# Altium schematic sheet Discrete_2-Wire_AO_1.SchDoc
size 431 x 279 mm; Date: Not shown in title block; ApprovedBy: Not shown in title block; CheckedBy: Not shown in title block; Author: Not shown in title block; CompanyName: Not shown in title block; Engineer: Not shown in title block; Organization: Not shown in title block; Address1: Not shown in title block; Address2: Not shown in title block; Address3: Not shown in title block; Address4: Not shown in title block; DocumentNumber: 1; Revision: Use project parameter SCH_Rev; SheetNumber: 1; SheetTotal: 1; PageSetup: Record=PageOptions|CenterHorizontal=True|CenterVertical=True|PrintScale=1.00|XCorrection=1.00|YCorrection=1.00|PrintKind=0|BorderSize=5000000|LeftOffset=0|BottomOffset=0|Orientation=2|PaperLength=1000|PaperWidth=1000|Scale=100|PaperSource=15|PrintQuality=600|MediaType=1|DitherType=10|PaperKind=Letter|PrintScaleMode=1
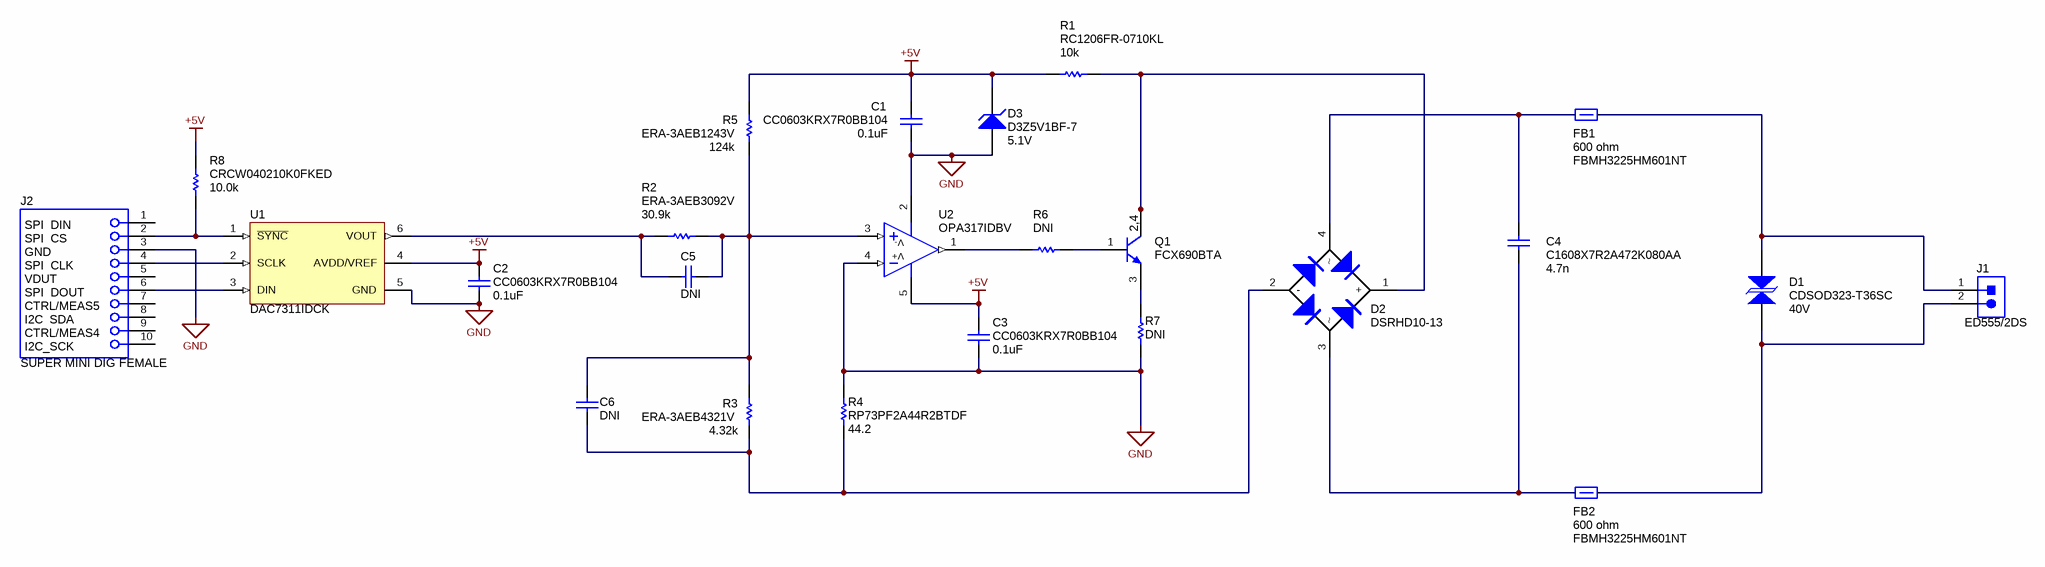
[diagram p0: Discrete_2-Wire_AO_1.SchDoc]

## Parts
C1  CC0603KRX7R0BB104  value 0.1uF  [0603]
C2  CC0603KRX7R0BB104  value 0.1uF  [0603]
C3  CC0603KRX7R0BB104  value 0.1uF  [0603]
C4  C1608X7R2A472K080AA  value 4.7n  [0603]
C5  DNI  [0603]
C6  DNI  [0603]
D1  CDSOD323-T36SC  value 40V  [sod-323]
D2  DSRHD10-13  [T-MiniDIP]
D3  D3Z5V1BF-7  value 5.1V  [SOD-323F]
FB1  FBMH3225HM601NT  value 600 ohm  [1210_H25]
FB2  FBMH3225HM601NT  value 600 ohm  [1210_H25]
J1  ED555/2DS  [TERM_BLK_ED555-2DS]
J2  SUPER MINI DIG FEMALE  [CONN_851-43-010-20-001000]
Q1  FCX690BTA  [SOT-89-3]
R1  RC1206FR-0710KL  value 10k  [1210]
R2  ERA-3AEB3092V  value 30.9k  [0603]
R3  ERA-3AEB4321V  value 4.32k  [0603]
R4  RP73PF2A44R2BTDF  value 44.2  [0805]
R5  ERA-3AEB1243V  value 124k  [0603]
R6  DNI  [0603]
R7  DNI  [0603]
R8  CRCW040210K0FKED  value 10.0k  [0402]
U1  DAC7311IDCK  [DCK0006A_N]
U2  OPA317IDBV  [DBV0005A_N]

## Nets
+5V: C1.1 C2.1 C3.1 D3.1(K) R1.1 R5.2 R8.2 U1.4(AVDD/VREF) U2.5(V+)
GND: C1.2 C2.2 C3.2 D3.2(A) J2.3 R4.2 R7.1 U1.5(GND) U2.2(V-) U2.4(IN-)
NetC4_1: C4.1 D2.4 FB1.1
NetC4_2: C4.2 D2.3 FB2.1
NetC5_1: C5.1 R2.1 U1.6(VOUT)
NetC5_2: C5.2 C6.1 R2.2 R3.2 R5.1 U2.3(IN+)
NetC6_2: C6.2 D2.2(-) R3.1 R4.1
NetD1_1: D1.1 FB1.2 J1.1
NetD1_2: D1.2 FB2.2 J1.2
NetD2_1: D2.1(+) Q1.2(C) Q1.4(C) R1.2
NetJ2_2: J2.2 R8.1 U1.1(~{SYNC})
NetJ2_4: J2.4 U1.2(SCLK)
NetJ2_6: J2.6 U1.3(DIN)
NetQ1_1: Q1.1(B) R6.2
NetQ1_3: Q1.3(E) R7.2
NetR6_1: R6.1 U2.1(OUT)

Not connected (* = marked no-connect by the designer): J2 1 5 7 8 9 10

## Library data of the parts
C1-C3 = Capacitor: CAP CER 0.1UF 100V 10% X7R 0603; Manufacturer: Yageo; Polarized: N; U/M: EA
C4 = Capacitor: CAP CER 4700PF 100V 10% X7R 0603; Manufacturer: TDK; Polarized: N; U/M: EA
C5 C6 = GRM188R72A102KA01D: CompType: Capacitor
D1 = SMAJ15CA: TVS DIODE 36VWM 60VC SOD323; Manufacturer: Bourns Inc
D2 = DSRHD10-13: Diode, Switching-Bridge, 1000V, 1A, 5.0x1.21x6.2mm; Manufacturer: Diodes Inc.; U/M: EA; Vf_V: 1.15; Value2: 1.15V; Io_A: 1; Vr_V: 1000; TJmax_C: 150
D3 = D3Z5V1BF-7: Diode, Zener, 5.1V, 400mW, SOD-323F; Manufacturer: Diodes Inc.; SymbolCreator: a0412235; U/M: EA; Power_W: 0.4; Vz_V: 5.1; Value1: 0.4W; RJA_CperW: 313
FB1 FB2 = FBMH3225HM601NT: 3A Ferrite Bead, 600 ohm @ 100MHz, SMD; Manufacturer: Taiyo Yuden; Imax_A: 3; DCR_ohm: 0.042; Value1: 0.042 ohm; ZTyp@100MHz_Ohm: 600; U/M: EA
J1 = ED555/2DS: Terminal Block, 6A, 3.5mm Pitch, 2-Pos, TH; Manufacturer: On-Shore Technology; SymbolCreator: a0412235; CompType: Connector; U/M: EA
J2 = 851-43-010-20-001000: Receptacle, 50mil 10x1, R/A, TH; Manufacturer: Mill-Max; SymbolCreator: a0411947; U/M: EA
Q1 = FCX690BTA, Diodes Inc.: Transistor, NPN, 45V, 1A, SOT-89; CompType: BJT; PNP: 0; NPN: 1; Vceo_V: 45; Vcesat1_V: 0.08; Value: 0.08V; TaMin_C: -55; TaMax_C: 150; U/M: EA
R1 = Resistor: RES 10.0K OHM 1/4W 1% 1206 SMD; Manufacturer: Yageo; U/M: EA; Power_W: 0.25W, 1/4W; TempCo: ±100ppm/°C
R2 = Resistor: RES 30.9K OHM 1/10W .1% 0603 SMD; Manufacturer: Panasonic; U/M: EA; Tolerance_%: ±0.1%; Power_W: 0.1W, 1/10W; TempCo: ±25ppm/°C
R3 = Resistor: RES 4.32K OHM 1/10W .1% 0603 SMD; Manufacturer: Panasonic; U/M: EA; Tolerance_%: ±0.1%; Power_W: 0.1W, 1/10W; TempCo: ±25ppm/°C
R4 = Resistor: RES 44.2 OHM 1/4W 0.1% 0805; Manufacturer: TE Connectivity; U/M: EA; Power_W: 0.25W, 1/4W; TempCo: ±25ppm/°C
R5 = Resistor: RES 124K OHM 1/10W .1% 0603 SMD; Manufacturer: Panasonic; U/M: EA; Tolerance_%: ±0.1%; Power_W: 0.1W, 1/10W; TempCo: ±25ppm/°C
R6 R7 = Resistor
R8 = CRCW040210K0FKED: RES, 10.0k ohm, 1%, 0.063W, 0402; Manufacturer: Vishay-Dale; CompType: Resistor; Res_ohm: 10000; Value_Code: 10k0; Tolerance_%: 1; Power_W: 0.063; VDC_V: 50; TempCo: 100 ppm/C; EIA_Code: E96; U/M: EA
U1 = DAC7311IDCK: 2.0V to 5.5V, 80µA, 12-Bit, Low-Power, Single-Channel, Digital-to-Analog Converters in SC70 Package, DCK0006A; Alternate Manufacturer: None; Manufacturer: Texas Instruments; SymbolCreator: a0411947; CompType: IC; U/M: EA
U2 = OPA317IDBV: Low-Offset, Rail-to-Rail I/O Operational Amplifier, DBV0005A; Alternate Manufacturer: None; Manufacturer: Texas Instruments; CompType: IC; U/M: EA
